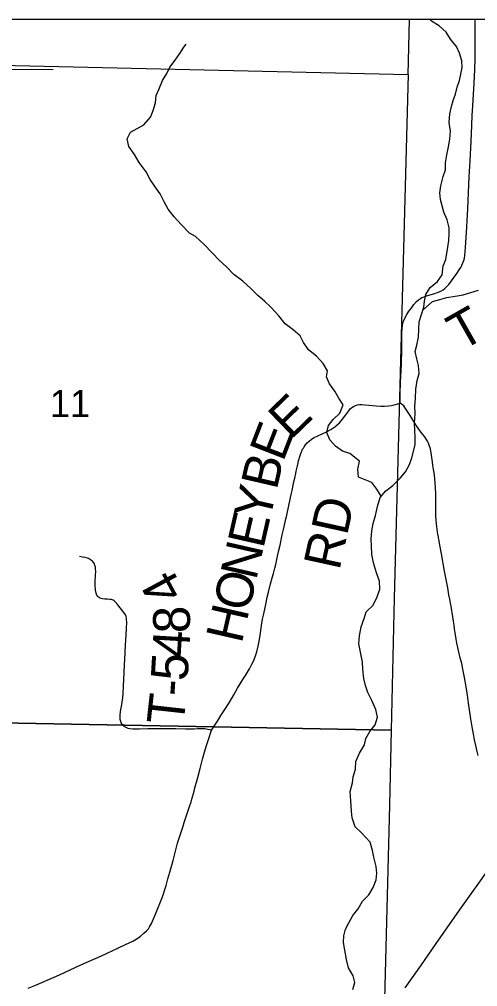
# Model space of a CAD drawing. Extents: x 0 to 191, y 0 to 55.
# Drawn here: x 143.75 to 144.102, y 24.673 to 25.418 of the extents above; entities that cross this region are included whole.
import ezdxf

# ---------------------------------------------------------------- set-up
doc = ezdxf.new("R2010")
doc.units = 0
for name, color, linetype in [('GM_X_Corporation', 7, 'Continuous'), ('GM_X_County_Road', 7, 'Continuous'), ('GM_X_Minor_River', 7, 'Continuous'), ('GM_X_Section_Text', 7, 'Continuous'), ('GM_X_Township_Road', 7, 'Continuous'), ('GM_X_Township_Road_Text', 7, 'Continuous')]:
    doc.layers.add(name, color=color, linetype=linetype)

msp = doc.modelspace()

# ---------------------------------------------------------------- linework, layer by layer
at = {"layer": 'GM_X_Corporation'}
for points in [[(149.5758, 25.41761), (143.27549, 25.41761), (143.27549, 22.87347), (143.3138, 22.87294), (143.47809, 22.86847), (143.4892, 23.25041), (143.50802, 23.86711), (143.51777, 23.86795), (143.52133, 23.86809), (143.52783, 23.86865), (143.53573, 23.86991), (143.5371, 23.871), (144.17888, 23.85682), (144.27104, 23.85429), (144.35683, 23.85102), (144.94266, 23.83902)], [(145.79254, 25.41761), (143.27549, 25.41761), (143.27549, 22.87347), (143.3138, 22.87294), (143.47809, 22.86847), (143.4892, 23.25041), (143.50802, 23.86711), (143.51777, 23.86795), (143.52133, 23.86809), (143.52783, 23.86865), (143.53573, 23.86991), (143.5371, 23.871), (144.17888, 23.85682), (144.27104, 23.85429), (144.35683, 23.85102), (144.94266, 23.83902)]]:
    msp.add_lwpolyline(points, dxfattribs=at)
for points in [[(144.04983, 25.41761), (143.54624, 25.41761), (143.54449, 25.38671), (144.04883, 25.37521)], [(143.54449, 25.38671), (144.04883, 25.37521), (144.04228, 25.12616), (144.03819, 24.9722), (144.03582, 24.87048), (143.5298, 24.88006)], [(144.03582, 24.87048), (144.03438, 24.81277), (144.0303, 24.65347), (144.02663, 24.49386), (144.02284, 24.36328), (143.51695, 24.37798), (143.5298, 24.88006)]]:
    msp.add_lwpolyline(points, close=True, dxfattribs=at)
at = {"layer": 'GM_X_County_Road'}
msp.add_lwpolyline([(144.04652, 24.67208), (144.05915, 24.68994), (144.07001, 24.70547), (144.07764, 24.71644), (144.08972, 24.73377), (144.09474, 24.74087), (144.10572, 24.75632), (144.11199, 24.7652), (144.12232, 24.77995), (144.1265, 24.78577), (144.12917, 24.78923), (144.13141, 24.79184), (144.13361, 24.79413)], dxfattribs=at)
at = {"layer": 'GM_X_Minor_River'}
for points in [[(144.07583, 25.22791), (144.07786, 25.23267), (144.07946, 25.24236), (144.08016, 25.24748), (144.08049, 25.25242), (144.08044, 25.25716), (144.07886, 25.2632), (144.07634, 25.26923), (144.07516, 25.27415), (144.07378, 25.27906), (144.07316, 25.28398), (144.07405, 25.28949), (144.07587, 25.29671), (144.07751, 25.30185), (144.07765, 25.30716), (144.07853, 25.31343), (144.07998, 25.31951), (144.08086, 25.3254), (144.08155, 25.33166), (144.08054, 25.33828), (144.08085, 25.34492), (144.08212, 25.35043), (144.08339, 25.35519), (144.08542, 25.35995), (144.0865, 25.36546), (144.08834, 25.37041), (144.08942, 25.37536), (144.09031, 25.38048), (144.09007, 25.3856), (144.08831, 25.39164), (144.08598, 25.39673), (144.08157, 25.40236), (144.07811, 25.40762), (144.07277, 25.41249), (144.06686, 25.4162), (144.06553, 25.41761)], [(144.02813, 25.05057), (144.02485, 25.0561), (144.02101, 25.06117), (144.01056, 25.06521), (144.01012, 25.07146), (144.01138, 25.07754), (144.00394, 25.08332), (143.99844, 25.08515), (143.99291, 25.08906), (143.9887, 25.09394), (143.98618, 25.09959), (143.98764, 25.10492), (143.99118, 25.1097), (143.99624, 25.1145), (143.99882, 25.12079), (143.99555, 25.12606), (143.99247, 25.13133), (143.98824, 25.13715), (143.98611, 25.14243), (143.98682, 25.14718), (143.98335, 25.15282), (143.97819, 25.15826), (143.97227, 25.1633), (143.96843, 25.16894), (143.96573, 25.17402), (143.96038, 25.17851), (143.95428, 25.18336), (143.9493, 25.18936), (143.94317, 25.19611), (143.93821, 25.20078), (143.93324, 25.20508), (143.92789, 25.21032), (143.92159, 25.21612), (143.91473, 25.22115), (143.90899, 25.22715), (143.90364, 25.23201), (143.89791, 25.23781), (143.89179, 25.24418), (143.88529, 25.25035), (143.88053, 25.25314), (143.87422, 25.25969), (143.86867, 25.2655), (143.86426, 25.27151), (143.86118, 25.27716), (143.85808, 25.28338), (143.85425, 25.28864), (143.8504, 25.29446), (143.84713, 25.30011), (143.84194, 25.30744), (143.8381, 25.31364), (143.83387, 25.31966), (143.83267, 25.32552), (143.83508, 25.33066), (143.84016, 25.33357), (143.84542, 25.33648), (143.85047, 25.34242), (143.85269, 25.34756), (143.85433, 25.35327), (143.85484, 25.35896), (143.85706, 25.36373), (143.85982, 25.37058), (143.86317, 25.37593), (143.86539, 25.3807), (143.8695, 25.38625), (143.87304, 25.39141), (143.8762, 25.39619), (143.87788, 25.39848)], [(144.0062, 24.67099), (144.00785, 24.67613), (144.00647, 24.68142), (144.003, 24.68745), (144.00142, 24.69387), (144.00021, 24.70125), (143.99901, 24.70712), (143.99934, 24.71205), (144.00061, 24.71738), (144.0032, 24.72215), (144.00636, 24.72788), (144.01047, 24.73305), (144.01381, 24.73897), (144.01868, 24.74377), (144.02183, 24.74949), (144.02423, 24.7554), (144.02474, 24.76053), (144.02431, 24.76545), (144.02253, 24.77283), (144.02153, 24.77774), (144.01957, 24.78417), (144.01287, 24.79148), (144.0081, 24.79597), (144.00575, 24.80295), (144.00513, 24.80806), (144.00467, 24.81602), (144.00422, 24.82322), (144.00604, 24.82988), (144.00656, 24.83463), (144.00839, 24.84034), (144.0087, 24.84641), (144.01147, 24.85289), (144.01519, 24.85919), (144.01627, 24.86394), (144.01943, 24.86948), (144.02354, 24.87465), (144.02537, 24.88055), (144.02398, 24.88641), (144.02088, 24.8932), (144.01779, 24.89942), (144.01603, 24.90489), (144.01465, 24.91037), (144.01401, 24.91738), (144.01376, 24.92287), (144.01237, 24.9293), (144.01078, 24.93687), (144.01147, 24.94313), (144.01272, 24.94997), (144.01511, 24.95645), (144.01657, 24.96158), (144.02181, 24.96677), (144.02496, 24.97306), (144.02698, 24.97897), (144.02691, 24.98522), (144.02458, 24.99164), (144.02223, 24.99919), (144.02102, 25.00581), (144.02077, 25.01225), (144.02033, 25.01737), (144.02083, 25.02401), (144.02191, 25.02952), (144.02374, 25.0358), (144.02518, 25.04264), (144.02719, 25.04949), (144.03167, 25.05466), (144.03711, 25.0589), (144.04273, 25.06447), (144.04684, 25.06945), (144.04981, 25.07499), (144.05165, 25.08013), (144.05419, 25.09021), (144.05413, 25.09608), (144.05407, 25.1012), (144.05382, 25.10688), (144.05432, 25.11409), (144.05407, 25.11997), (144.05439, 25.12566), (144.05488, 25.13287), (144.05575, 25.13951), (144.05721, 25.14503), (144.05695, 25.15128), (144.05558, 25.15638), (144.05438, 25.16205), (144.05566, 25.16681), (144.05692, 25.17308), (144.05704, 25.17915), (144.05736, 25.18465), (144.06103, 25.19606), (144.06154, 25.20081), (144.06244, 25.20594), (144.06579, 25.2111), (144.07141, 25.21591), (144.07495, 25.22107), (144.07583, 25.22791)], [(144.06033, 25.19389), (144.0676, 25.20032), (144.07326, 25.2019), (144.07873, 25.20349), (144.08515, 25.20452), (144.09119, 25.20554), (144.10307, 25.2091)]]:
    msp.add_lwpolyline(points, dxfattribs=at)
at = {"layer": 'GM_X_Township_Road'}
for points in [[(144.04259, 25.12224), (144.04262, 25.12924), (144.04294, 25.13797), (144.04362, 25.15228), (144.04394, 25.16356), (144.04404, 25.17111), (144.04401, 25.17645), (144.0442, 25.17944), (144.04461, 25.1822), (144.0454, 25.1852), (144.04652, 25.1881), (144.04778, 25.1904), (144.04949, 25.19293), (144.05113, 25.19511), (144.0533, 25.19806), (144.05533, 25.20045), (144.05675, 25.20165), (144.05826, 25.20272), (144.05932, 25.2034), (144.06045, 25.20388), (144.06308, 25.20483), (144.06935, 25.20663), (144.072, 25.20752), (144.07399, 25.20841), (144.07586, 25.20952), (144.07709, 25.21046), (144.07823, 25.2115), (144.0801, 25.21358), (144.08218, 25.21629), (144.08638, 25.22208), (144.08809, 25.22468), (144.08933, 25.22668), (144.09029, 25.2285), (144.09107, 25.23028), (144.09168, 25.23195), (144.09214, 25.2337), (144.09246, 25.2358), (144.09299, 25.24211), (144.09378, 25.25358), (144.09454, 25.26692), (144.09499, 25.27778), (144.09524, 25.28429), (144.09578, 25.29639), (144.09651, 25.30879), (144.09732, 25.32368), (144.09788, 25.3361), (144.09824, 25.34354), (144.09861, 25.35099), (144.09886, 25.35533), (144.09961, 25.36836), (144.10009, 25.37891), (144.10033, 25.38698), (144.10051, 25.39848), (144.10053, 25.40624), (144.10055, 25.41246), (144.10041, 25.4165), (144.1003, 25.41761)], [(143.72646, 25.37917), (143.77573, 25.379)], [(143.89758, 24.87049), (143.89847, 24.87204), (143.89953, 24.87368), (143.90056, 24.87518), (143.90107, 24.87594), (143.90208, 24.87748), (143.90289, 24.87879), (143.9047, 24.88168), (143.90724, 24.88558), (143.911, 24.89164), (143.91465, 24.89779), (143.91762, 24.90289), (143.91955, 24.90608), (143.92166, 24.90951), (143.92363, 24.91266), (143.92671, 24.9177), (143.92863, 24.92125), (143.92971, 24.92348), (143.9311, 24.92694), (143.93231, 24.93079), (143.93335, 24.93501), (143.93415, 24.93897), (143.93485, 24.94326), (143.93602, 24.95094), (143.93686, 24.95584), (143.93766, 24.96011), (143.93947, 24.96861), (143.94045, 24.97284), (143.94139, 24.97676), (143.943, 24.98307), (143.9443, 24.98786), (143.94519, 24.99116), (143.94596, 24.99415), (143.94619, 24.99506), (143.94694, 24.99805), (143.94786, 25.00197), (143.94814, 25.00318), (143.94918, 25.00803), (143.95022, 25.0129), (143.95173, 25.01955), (143.95201, 25.02075), (143.95294, 25.02499), (143.95449, 25.03182), (143.95482, 25.0332), (143.95514, 25.03469), (143.95539, 25.03588), (143.95832, 25.04948), (143.95903, 25.05282), (143.95952, 25.05495), (143.9607, 25.06041), (143.96115, 25.06253), (143.96153, 25.06435), (143.96229, 25.06801), (143.96267, 25.06982), (143.96317, 25.07192), (143.96359, 25.07405), (143.96411, 25.07615), (143.96446, 25.07797), (143.96486, 25.07943), (143.96512, 25.08031), (143.96539, 25.08113), (143.96619, 25.08332), (143.96669, 25.08473), (143.96692, 25.08526), (143.96722, 25.08593), (143.96762, 25.08678), (143.96825, 25.08765), (143.96876, 25.08867), (143.9699, 25.09004), (143.97117, 25.09166), (143.97305, 25.09323), (143.97427, 25.09416), (143.97606, 25.09542), (143.97935, 25.09707), (143.98271, 25.09867), (143.98606, 25.10022), (143.98933, 25.10198), (143.99244, 25.10403), (143.99412, 25.1054), (143.99595, 25.10706), (143.99839, 25.10985), (144.00077, 25.11309), (144.00313, 25.11635), (144.00434, 25.11774), (144.00547, 25.11878), (144.00673, 25.11965), (144.0084, 25.12041), (144.00987, 25.12082), (144.01139, 25.12103), (144.01325, 25.1211), (144.01542, 25.121), (144.0185, 25.12067), (144.02435, 25.12005), (144.02776, 25.1199), (144.03055, 25.11991), (144.03363, 25.12014), (144.0361, 25.12049), (144.03821, 25.12098), (144.04259, 25.12224)], [(144.10273, 24.85094), (144.10199, 24.85412), (144.10094, 24.85878), (144.10005, 24.86303), (144.09943, 24.86607), (144.09813, 24.87308), (144.09711, 24.87921), (144.09538, 24.8912), (144.09455, 24.89735), (144.09357, 24.90379), (144.0923, 24.91111), (144.09102, 24.91749), (144.09006, 24.92173), (144.08898, 24.92626), (144.08766, 24.93169), (144.08634, 24.93743), (144.08574, 24.94048), (144.08496, 24.94538), (144.08454, 24.94846), (144.08417, 24.95123), (144.08375, 24.9543), (144.08325, 24.95768), (144.08189, 24.96592), (144.08123, 24.96958), (144.08088, 24.97141), (144.08027, 24.97477), (144.0793, 24.97996), (144.07693, 24.99279), (144.07452, 25.00625), (144.07277, 25.01564), (144.07264, 25.01645), (144.07227, 25.01849), (144.0721, 25.01941), (144.07196, 25.02028), (144.07179, 25.0212), (144.07114, 25.0251), (144.07057, 25.02938), (144.0703, 25.03246), (144.07017, 25.03525), (144.0701, 25.04053), (144.07004, 25.05202), (144.06987, 25.05729), (144.06966, 25.0607), (144.06935, 25.0641), (144.06878, 25.06872), (144.06845, 25.07119), (144.06797, 25.07426), (144.06756, 25.077), (144.06714, 25.08037), (144.06664, 25.08403), (144.06601, 25.08703), (144.06514, 25.08985), (144.0645, 25.09138), (144.06376, 25.09293), (144.06163, 25.0962), (144.059, 25.09968), (144.05468, 25.1054), (144.05031, 25.11278), (144.04623, 25.11893), (144.04543, 25.12), (144.04477, 25.12071), (144.04352, 25.12169), (144.04259, 25.12224)], [(143.89758, 24.87049), (143.89334, 24.87133), (143.89229, 24.87147), (143.89105, 24.87154), (143.88906, 24.87156), (143.88659, 24.87146), (143.88411, 24.87137), (143.87758, 24.87135), (143.87012, 24.87148), (143.85645, 24.87156), (143.85147, 24.87153), (143.84837, 24.87151), (143.84215, 24.87136), (143.83966, 24.87129), (143.83685, 24.87133), (143.83465, 24.8716), (143.83347, 24.87186), (143.83169, 24.87257), (143.83038, 24.87334), (143.82942, 24.87407), (143.82865, 24.87502), (143.82797, 24.87606), (143.82741, 24.8778), (143.82722, 24.87871), (143.82715, 24.88056), (143.82724, 24.88242), (143.82783, 24.88643), (143.82822, 24.88858), (143.82878, 24.89195), (143.82922, 24.89533), (143.82951, 24.89873), (143.82986, 24.9043), (143.83028, 24.91486), (143.83054, 24.92075), (143.83074, 24.92482), (143.8313, 24.93588), (143.83171, 24.94368), (143.83198, 24.949), (143.83232, 24.95352), (143.83217, 24.95578), (143.83206, 24.95645), (143.83171, 24.95786), (143.83119, 24.95914), (143.82995, 24.96099), (143.82816, 24.9633), (143.82611, 24.96594), (143.82457, 24.96788), (143.8235, 24.96913), (143.82248, 24.97), (143.82173, 24.97049), (143.82109, 24.97079), (143.82018, 24.97102), (143.81935, 24.97117), (143.81735, 24.97129), (143.81536, 24.97142), (143.81357, 24.97153), (143.81249, 24.97178), (143.81192, 24.972), (143.81131, 24.97227), (143.81041, 24.9729), (143.81, 24.97332), (143.80936, 24.97434), (143.80892, 24.9752), (143.80864, 24.97596), (143.80828, 24.97812), (143.8082, 24.97916), (143.808, 24.98143), (143.80807, 24.98467), (143.80819, 24.98968), (143.80835, 24.99293), (143.80831, 24.99429), (143.80815, 24.99582), (143.80778, 24.99731), (143.80733, 24.99845), (143.80671, 24.99951), (143.80594, 25.00048), (143.80517, 25.00119), (143.80447, 25.0017), (143.80363, 25.00213), (143.80279, 25.00253), (143.80193, 25.00284), (143.80027, 25.00329), (143.79812, 25.00371), (143.79586, 25.00405)], [(143.75644, 24.67182), (143.76156, 24.67407), (143.765, 24.6755), (143.76929, 24.67727), (143.77644, 24.68035), (143.78054, 24.68212), (143.79682, 24.68984), (143.81282, 24.6968), (143.82151, 24.70092), (143.83122, 24.70547), (143.83695, 24.70816), (143.83955, 24.70959), (143.84069, 24.71035), (143.84284, 24.71201), (143.84552, 24.71432), (143.8475, 24.71608), (143.84895, 24.71764), (143.84986, 24.71898), (143.85131, 24.72166), (143.85447, 24.72873), (143.85977, 24.74212), (143.8625, 24.75085), (143.86396, 24.75599), (143.86543, 24.76121), (143.86786, 24.77024), (143.87061, 24.7805), (143.87139, 24.78339), (143.8736, 24.7905), (143.87533, 24.79581), (143.87651, 24.79935), (143.87807, 24.80406), (143.88059, 24.81173), (143.88172, 24.81528), (143.88235, 24.81736), (143.88415, 24.82363), (143.88476, 24.82603), (143.88689, 24.83414), (143.88869, 24.84105), (143.89062, 24.84825), (143.89269, 24.85541), (143.89369, 24.85867), (143.89532, 24.86406), (143.89723, 24.8696), (143.89758, 24.87049)]]:
    msp.add_lwpolyline(points, dxfattribs=at)

# ---------------------------------------------------------------- texts
at = {"layer": 'GM_X_Section_Text'}
msp.add_text('11', height=0.020928, rotation=0.00001, dxfattribs=at).set_placement((143.77303, 25.11143))
at = {"layer": 'GM_X_Township_Road_Text'}
for s, height, rotation, p in [('T', 0.02841, 29.60241, (144.08975, 25.16188)), ('E', 0.02841, 44.09388, (143.95847, 25.09351)), ('E', 0.02841, 68.78987, (143.95255, 25.07638)), ('B', 0.02841, 77.02117, (143.94763, 25.05467)), ('Y', 0.02841, 77.16362, (143.94208, 25.03032)), ('RD', 0.028409, 77.6328, (143.99589, 24.99279)), ('E', 0.02841, 77.1602, (143.93736, 25.0096)), ('N', 0.02841, 77.16362, (143.9318, 24.98522)), ('4', 0.02841, 118.37715, (143.8771, 24.97693)), ('O', 0.02841, 77.16142, (143.92625, 24.96085)), ('8', 0.02841, 91.13666, (143.88116, 24.94533)), ('H', 0.02841, 77.16497, (143.9207, 24.93647)), ('4', 0.02841, 86.64807, (143.88009, 24.92543)), ('5', 0.02841, 86.51086, (143.87902, 24.90789)), ('-', 0.02841, 86.24912, (143.87825, 24.89611)), ('T', 0.02841, 83.70901, (143.8758, 24.87362))]:
    msp.add_text(s, height=height, rotation=rotation, dxfattribs=at).set_placement(p)

doc.saveas('drawing.dxf')
